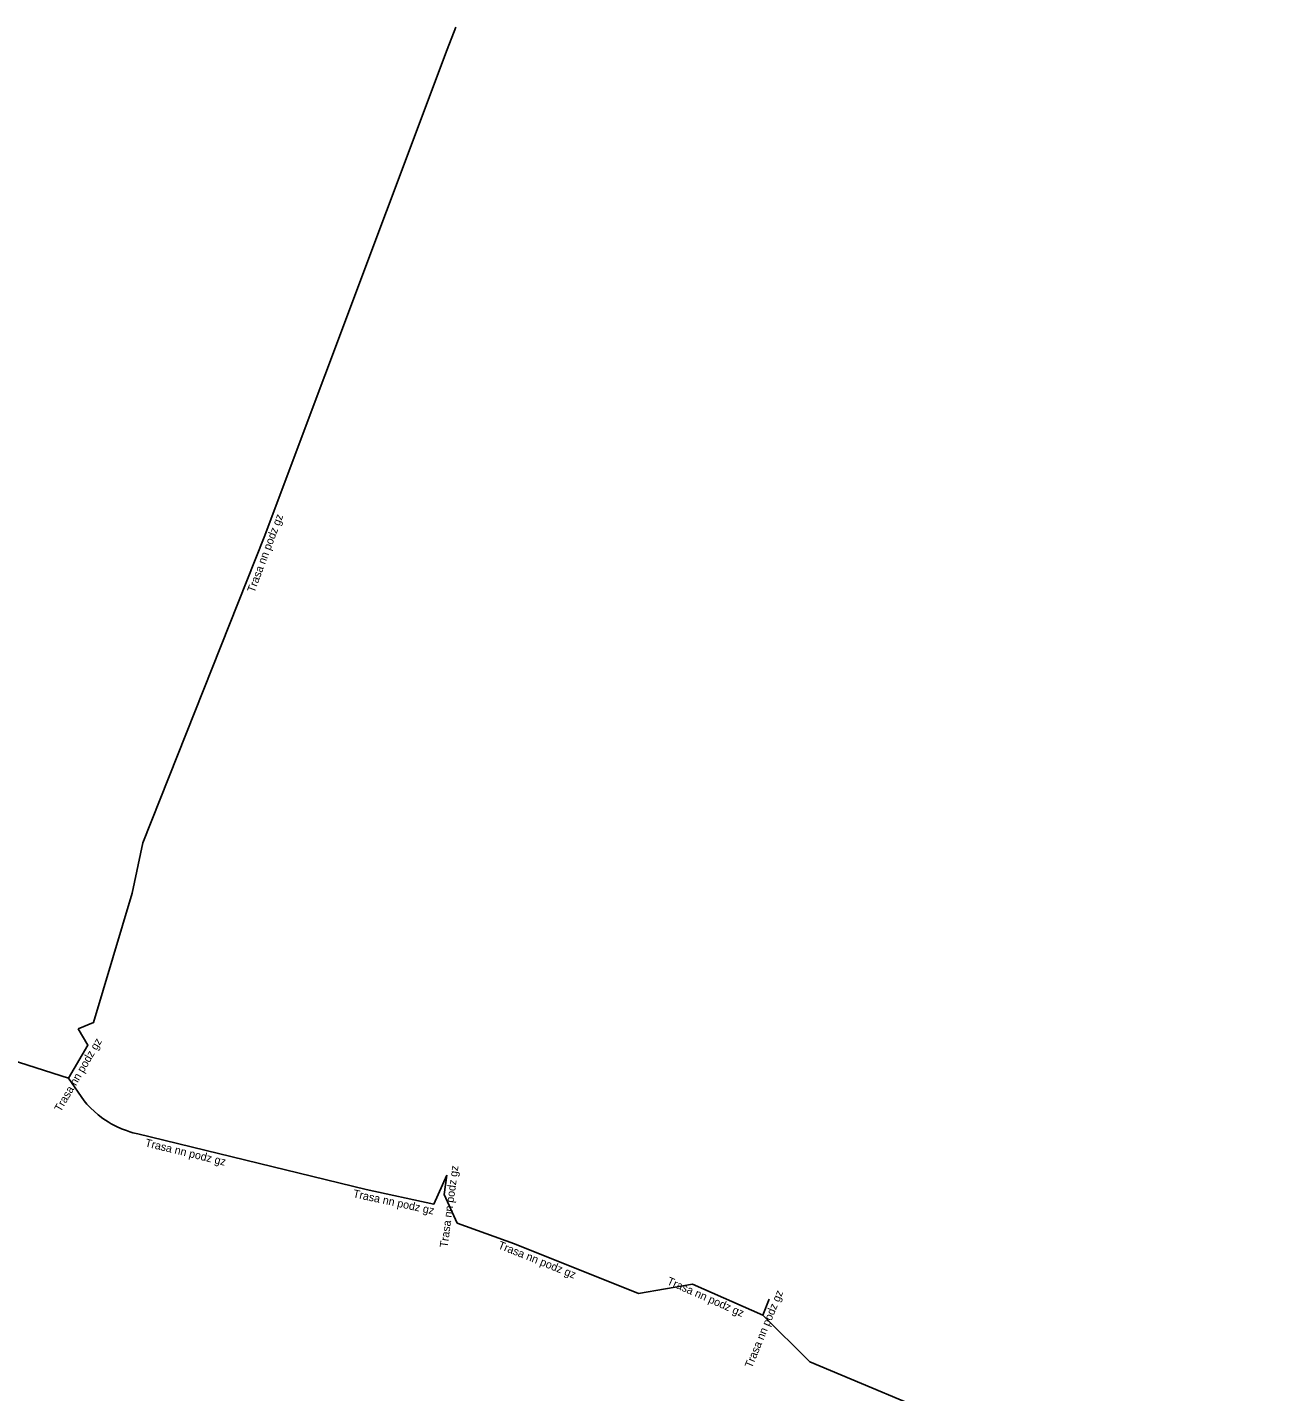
# Model space of a CAD drawing. Extents: x -771647 to -771045, y -1049993 to -1049764.
# Drawn here: x -771273.2 to -771195.8, y -1049888.9 to -1049803.6 of the extents above; entities that cross this region are included whole.
import ezdxf

# ---------------------------------------------------------------- set-up
doc = ezdxf.new("R2010")
doc.units = 0
doc.layers.add('Popiskový text - Ostatní atributy Trasy', color=7, linetype='Continuous')
doc.layers.add('Spojnice NN', color=7, linetype='Continuous')

msp = doc.modelspace()

# ---------------------------------------------------------------- linework, layer by layer
at = {"layer": 'Spojnice NN'}
for points in [[(-771246.424, -1049803.621), (-771246.97, -1049805), (-771258.39, -1049835.47), (-771265.98, -1049854.58), (-771266.65, -1049857.72), (-771269.06, -1049865.79), (-771270.027, -1049866.18)], [(-771303.573, -1049863.345), (-771303.566, -1049863.658), (-771303.544, -1049863.816), (-771303.508, -1049863.988), (-771303.463, -1049864.138), (-771303.391, -1049864.324), (-771303.307, -1049864.492), (-771303.157, -1049864.728), (-771302.999, -1049864.92), (-771302.856, -1049865.059), (-771302.678, -1049865.204), (-771302.48, -1049865.33), (-771274.72, -1049867.96), (-771270.62, -1049869.28)], [(-771270.027, -1049866.18), (-771269.411, -1049867.203), (-771270.62, -1049869.28)], [(-771270.62, -1049869.28), (-771269.65, -1049870.68), (-771269.474, -1049870.887), (-771269.23, -1049871.145), (-771269.023, -1049871.34), (-771268.765, -1049871.561), (-771268.471, -1049871.786), (-771268.144, -1049872.001), (-771267.948, -1049872.12), (-771267.631, -1049872.29), (-771267.306, -1049872.435), (-771267.003, -1049872.552), (-771266.781, -1049872.629), (-771266.594, -1049872.685), (-771266.29, -1049872.76), (-771252.015, -1049876.226)], [(-771246.986, -1049875.325), (-771247.797, -1049877.139), (-771252.015, -1049876.226)], [(-771246.986, -1049875.325), (-771247.149, -1049876.542)], [(-771247.149, -1049876.542), (-771246.33, -1049878.33), (-771242.76, -1049879.62), (-771235.001, -1049882.719), (-771231.644, -1049882.133)], [(-771227.251, -1049884.068), (-771231.644, -1049882.133)], [(-771226.842, -1049883.077), (-771227.251, -1049884.068)], [(-771227.251, -1049884.068), (-771224.307, -1049886.999), (-771214.88, -1049890.94), (-771209.86, -1049891.2), (-771196.109, -1049896.733), (-771195.823, -1049896.814)]]:
    msp.add_lwpolyline(points, dxfattribs=at)

# ---------------------------------------------------------------- texts
at = {"layer": 'Popiskový text - Ostatní atributy Trasy'}
for rotation, p in [(69.45426, (-771259.01, -1049838.977)), (59.79676, (-771271.112, -1049871.418)), (346.35256, (-771265.873, -1049873.53)), (82.37144, (-771246.94, -1049879.879)), (347.78655, (-771252.878, -1049876.705)), (338.22629, (-771243.831, -1049879.892)), (336.22778, (-771233.273, -1049882.126)), (67.57335, (-771227.931, -1049887.42))]:
    msp.add_text('Trasa nn podz gz', height=0.5, rotation=rotation, dxfattribs=at).set_placement(p)

doc.saveas('drawing.dxf')
